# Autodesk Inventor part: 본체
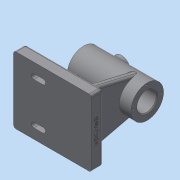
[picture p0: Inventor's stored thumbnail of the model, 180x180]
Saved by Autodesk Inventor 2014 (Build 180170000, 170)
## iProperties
Created: 2026-09
Part Number: 본체
Material: 일반
Document SubType Name: Modeling
Designer: dg
Density: 1 g/cm^3
Appearance: 기본값
Author: dg
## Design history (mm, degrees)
sketch "스케치1"
  geometry: L1 (-41, 0)-(41, 0); L2 (-41, 14.5)-(21, 14.5); L3 (21, 14.5)-(21, 12.5); L4 (21, 12.5)-(41, 12.5); L5 (41, 12.5)-(41, 21); L6 (41, 21)-(-41, 21); L7 (-41, 21)-(-41, 14.5); 2 further points
  constraints: 14 end point, 5 parallel, 2 vertical alignment, 1 coincident, 1 horizontal, 1 midpoint, 1 perpendicular
  dimensions: "d0" = 82 distance of L1.start L1.end; "d1" = 25 diameter of L4 L1; "d2" = 29 diameter of L2 L1; "d3" = 42 diameter of L6 L1; "d4" = 62 distance between parallel lines of L3 L7
revolve "회전1" sketch "스케치1" stored, may be unused: angle "d5" = 90 deg
node "작업 평면1"
sketch "스케치2"
  geometry: L1 (41, 21)-(41, -21) reference; L2 (-41, 21)-(-41, -21) reference; L3 (59, -43)-(-41, -43); L4 (-41, -43)-(-41, 43); L5 (-41, 43)-(59, 43); L6 (59, 43)-(59, -43); 2 further points
  constraints: 8 end point, 2 midpoint, 2 parallel, 1 horizontal, 1 perpendicular
  dimensions: "d7" = 100 distance of L3.start L3.end; "d8" = 86 distance of L5.end L3.start
extrude "돌출1" join sketch "스케치2" distance "d9" = 15; taper "d10" = 0 deg
node "작업 평면2"
sketch "스케치3"
  geometry: L1 (41, 21)-(41, -21) reference; C1 r 11 at (16, 0); 1 further point
  constraints: 1 centre point, 1 horizontal alignment
  dimensions: "d12" = 22 diameter of C1; "d13" = 25 distance from line of C1.centre L1
extrude "돌출2" join sketch "스케치3" stored distance "d14" = 15; taper "d15" = 0 deg
hole "구멍1" diameter "d18" = 4.917; stored, may be unused: countersink angle "d22" = 90 deg, drill point angle "d24" = 118 deg; dims "d19" = 10, "d20" = 14, "d21" = 4, "d23" = 8, "d25" = 10, "d26" = 10
node "작업 평면3"
sketch "스케치4"
  geometry: L1 (86, 0)-(0, 0) reference; L2 (86, 0)-(86, 15) reference; L3 (0, 15)-(86, 15) reference; L4 (0, 0)-(0, 15) reference; L5 (22.559, 76.814)-(8, 15); L6 (63.441, 76.814)-(78, 15); C1 r 12.5 at (43, 72) reference; C2 r 21 at (43, 72) reference; A1 r 21 centre (43, 72) between (22.559, 76.814) and (63.441, 76.814) reference; 1 further point
  constraints: 4 end point, 2 point on circle, 2 point on line, 2 tangent
  dimensions: "d30" = 8 distance from line of L4 L5.end; "d31" = 8 distance from line of L6.end L2
extrude "돌출3" join sketch "스케치4" distance "d32" = 10; taper "d33" = 0 deg
sketch "스케치5"
  geometry: L1 (-41, 21)-(-27, 21) reference; L2 (-27, 21)-(-27, 24) reference; L3 (-27, 24)-(-23, 24) reference; L4 (-23, 24)-(-23, 20) reference; L5 (-23, 20)-(-18.458, 20) reference; L6 (-18.458, 20)-(-18.458, 14.5) reference; L7 (-18.458, 14.5)-(-41, 14.5) reference; L8 (-41, 14.5)-(-41, 21) reference; L9 (-5, 21)-(41, 21) reference; L10 (41, 21)-(41, 12.5) reference; L11 (41, 12.5)-(21, 12.5) reference; L12 (21, 12.5)-(21, 14.5) reference; L13 (21, 14.5)-(-13.541, 14.5) reference; L14 (-13.541, 14.5)-(-13.541, 20) reference; L15 (-13.541, 20)-(-9, 20) reference; L16 (-9, 20)-(-9, 24) reference; L17 (-9, 24)-(-5, 24) reference; L18 (-5, 24)-(-5, 21) reference; L19 (-41, -14.5)-(21, -14.5) reference; L20 (21, -14.5)-(21, -12.5) reference; L21 (21, -12.5)-(41, -12.5) reference; L22 (41, -12.5)-(41, -21) reference; L23 (41, -21)-(26, -21) reference; L24 (26, -21)-(26, -57) reference; L25 (26, -57)-(41, -57) reference; L26 (41, -57)-(41, -72) reference; L27 (41, -72)-(-59, -72) reference; L28 (-59, -72)-(-59, -57) reference; L29 (-59, -57)-(16, -57) reference; L30 (16, -57)-(16, -21) reference; L31 (16, -21)-(-41, -21) reference; L32 (-41, -21)-(-41, -14.5) reference; L33 (-44, -57)-(-30.897, -21); 1 further point
  constraints: 2 end point, 2 point on line
  dimensions: "d34" = 15 distance from line of L33.start L28; "d35" = 70 deg angle of L29 L33
feature "리브1" sketch "스케치5" dims "d36" = 1, "d37" = 10, "d38" = 0, "d39" = 0, "d40" = 1, "d41" = 1
sketch "스케치6"
  geometry: C1 r 14.5 at (0, 0) reference; 1 further point
  constraints: 1 vertical alignment
  dimensions: "d42" = 18 distance of point (0, 18) C1.centre
hole "구멍2" sketch "스케치6" at (0, 18) diameter "d43" = 2.459; stored, may be unused: countersink angle "d47" = 90 deg, drill point angle "d49" = 118 deg; dims "d44" = 8, "d45" = 14, "d46" = 4, "d48" = 10
chamfer "모따기1" distance "d53" = 1; stored, may be unused: second distance "d54" = 2, angle "d55" = 45 deg
sketch "스케치7"
  geometry: L1 (41, 43)-(-59, 43) reference; L2 (-59, 43)-(-59, -43) reference; L3 (-33, -27)-(-21, -27); L4 (-33, -34)-(-21, -34); L5 (-21, -20)-(-33, -20); L6 (-33, 27)-(-21, 27); L7 (-33, 20)-(-21, 20); L8 (-21, 34)-(-33, 34); L9 (-33, 30.3)-(-21, 30.3); L10 (-21, 23.7)-(-33, 23.7); L11 (-33, -23.7)-(-21, -23.7); L12 (-21, -30.3)-(-33, -30.3); A1 r 7 centre (-33, -27) between (-33, -20) and (-33, -34); A2 r 7 centre (-21, -27) between (-21, -34) and (-21, -20); A3 r 7 centre (-33, 27) between (-33, 34) and (-33, 20); A4 r 7 centre (-21, 27) between (-21, 20) and (-21, 34); A5 r 3.3 centre (-21, 27) between (-21, 23.7) and (-21, 30.3); A6 r 3.3 centre (-33, 27) between (-33, 30.3) and (-33, 23.7); A7 r 3.3 centre (-21, -27) between (-21, -30.3) and (-21, -23.7); A8 r 3.3 centre (-33, -27) between (-33, -23.7) and (-33, -30.3); 3 further points
  constraints: 24 end point, 16 point on circle, 8 centre point, 8 tangent, 7 parallel, 2 equal radius, 2 midpoint, 1 vertical alignment, 6 other
  dimensions: "d56" = 27 horizontal distance of point (-27, 27) point (0, 0); "d57" = 27 horizontal distance of point (-27, -27) point (0, 0); "d58" = 12 distance of L6.start L6.end; "d59" = 14 distance between parallel lines of L7 L8; "d60" = 26 distance from line of L3.start L2; "d61" = 6.6 distance between parallel lines of L10 L9
extrude "돌출4" join sketch "스케치7" distance "d62" = 3; taper "d63" = 0 deg
extrude "돌출5" cut sketch "스케치7" stored distance "d64" = 3; taper "d65" = 0 deg
sketch "스케치8"
  geometry: L1 (86, 0)-(0, 0) reference; 2 further points
  constraints: 1 vertical alignment, 1 other
  dimensions: "d67" = 6 distance from line of point (43, 6) L1
extrude "돌출6" join sketch "스케치8" distance "d68" = 0.5; taper "d69" = 0 deg
fillet "모깎기1" dims "d70" = 3
fillet "모깎기2" dims "d71" = 3
fillet "모깎기3" dims "d72" = 3
fillet "모깎기4" dims "d73" = 3
fillet "모깎기5" dims "d74" = 3
node "솔리드1"
pattern_circular "원형 패턴1" dims angle "d51" = 360 deg
mirror "대칭1"
node "투영된 루프1"
node "투영된 루프2"
node "투영된 루프3"
node "절단 모서리 투영1"
other parameters: "d6" = -72, "d11" = 24, "d27" = -15
